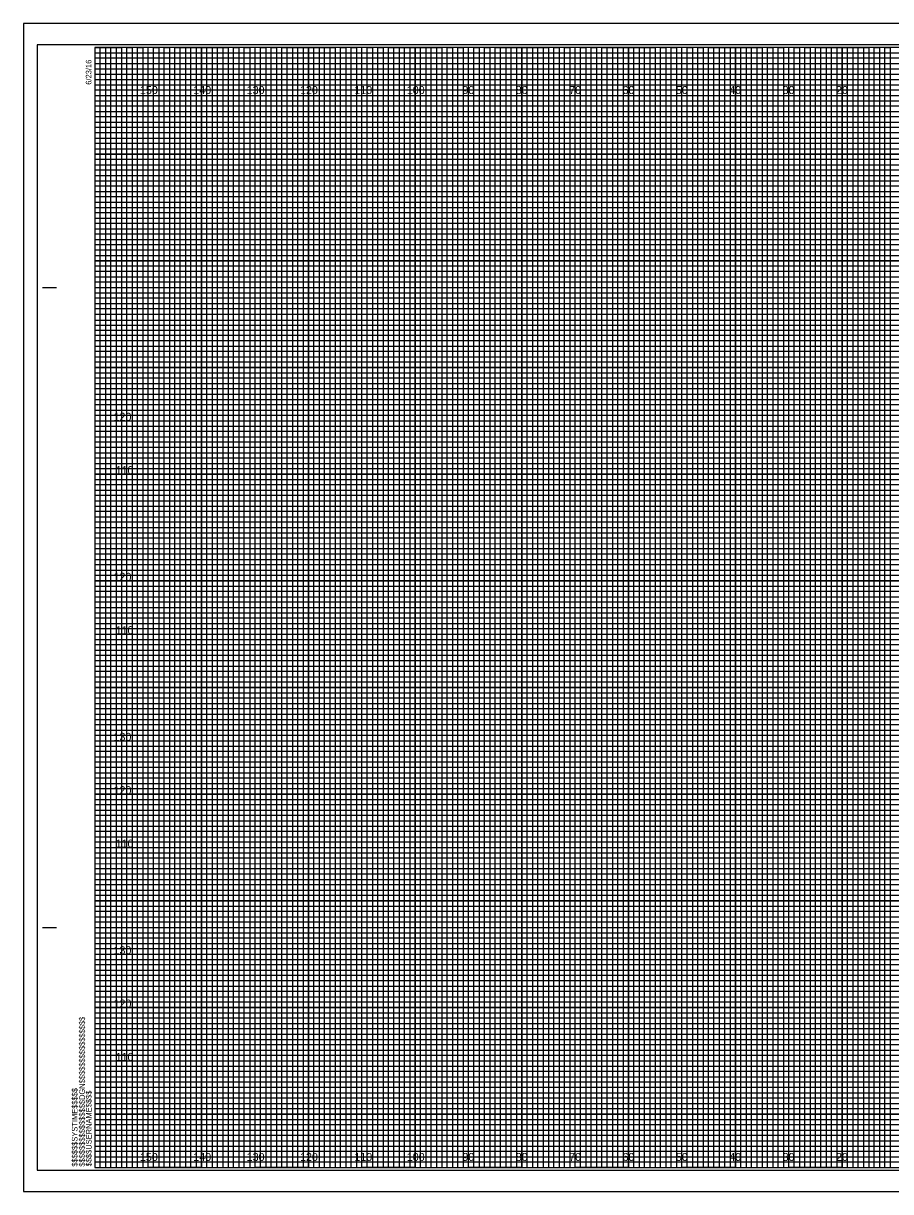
# Model space of a CAD drawing. Extents: x -13 to 323, y -5 to 215.
# Drawn here: x -13.4 to 149.1, y -4.5 to 214.5 of the extents above; entities that cross this region are included whole.
import ezdxf

# ---------------------------------------------------------------- set-up
doc = ezdxf.new("R2010")
doc.units = 0
for name, color, linetype in [('Prop XS Elevation Labels', 7, 'Continuous'), ('Prop XS Offset Labels', 7, 'Continuous'), ('Sheet Cross Section CELL', 7, 'Continuous'), ('Sheet Cross Section Grid Major CELL', 7, 'Continuous'), ('Sheet Cross Section Grid Middle CELL', 7, 'Continuous'), ('Sheet Cross Section Grid Minor 1 CELL', 7, 'Continuous'), ('Sheet Cross Section Grid Minor 2 CELL', 7, 'Continuous'), ('Sheet Cutting Line CELL', 7, 'Continuous'), ('Sheet DOT Grid CELL', 7, 'Continuous'), ('Sheet Plot Border Inside CELL', 7, 'Continuous'), ('Sheet Plot Border Outside CELL', 7, 'Continuous')]:
    doc.layers.add(name, color=color, linetype=linetype)

msp = doc.modelspace()

# ---------------------------------------------------------------- linework, layer by layer
at = {"layer": 'Sheet Cross Section CELL'}
for p, q in [((-9.8, 165), (-7.3, 165)), ((-9.7, 165), (-7.2, 165)), ((-9.8, 45), (-7.3, 45)), ((-9.7, 45), (-7.2, 45)), ((0, 0), (0, 0)), ((0, 0), (0, 0)), ((0, 0), (0, 0)), ((0, 0), (0, 0)), ((0, 0), (0, 0)), ((0, 0), (0, 0)), ((0, 0), (0, 0))]:
    msp.add_line(p, q, dxfattribs=at)
msp.add_lwpolyline([(320, 210), (0, 210), (0, 0), (320, 0)], close=True, dxfattribs=at)
at = {"layer": 'Sheet Cross Section Grid Major CELL'}
for p, q in [((10, 210), (0, 210)), ((10, 0), (10, 210)), ((30, 210), (20, 210)), ((20, 210), (20, 0)), ((30, 0), (30, 210)), ((50, 210), (40, 210)), ((40, 210), (40, 0)), ((50, 0), (50, 210)), ((70, 210), (60, 210)), ((60, 210), (60, 0)), ((70, 0), (70, 210)), ((90, 210), (80, 210)), ((80, 210), (80, 0)), ((90, 0), (90, 210)), ((110, 210), (100, 210)), ((100, 210), (100, 0)), ((110, 0), (110, 210)), ((130, 210), (120, 210)), ((120, 210), (120, 0)), ((130, 0), (130, 210)), ((150, 210), (140, 210)), ((140, 210), (140, 0)), ((20, 0), (10, 0)), ((40, 0), (30, 0)), ((60, 0), (50, 0)), ((80, 0), (70, 0)), ((100, 0), (90, 0)), ((120, 0), (110, 0)), ((140, 0), (130, 0))]:
    msp.add_line(p, q, dxfattribs=at)
for points in [[(0, 200), (320, 200), (320, 190), (0, 190)], [(0, 180), (320, 180), (320, 170), (0, 170)], [(0, 160), (320, 160), (320, 150), (0, 150)], [(0, 140), (320, 140), (320, 130), (0, 130)], [(0, 120), (320, 120), (320, 110), (0, 110)], [(0, 100), (320, 100), (320, 90), (0, 90)], [(0, 80), (320, 80), (320, 70), (0, 70)], [(0, 60), (320, 60), (320, 50), (0, 50)], [(0, 40), (320, 40), (320, 30), (0, 30)], [(0, 20), (320, 20), (320, 10), (0, 10)]]:
    msp.add_lwpolyline(points, dxfattribs=at)
at = {"layer": 'Sheet Cross Section Grid Middle CELL'}
for points in [[(0, 210), (5, 210), (5, 0), (15, 0), (15, 210), (25, 210), (25, 0), (35, 0), (35, 210), (45, 210), (45, 0), (55, 0), (55, 210), (65, 210), (65, 0), (75, 0), (75, 210), (85, 210), (85, 0), (95, 0), (95, 210), (105, 210), (105, 0), (115, 0), (115, 210), (125, 210), (125, 0), (135, 0), (135, 210), (145, 210), (145, 0), (155, 0)], [(0, 205), (275, 205)], [(0, 185), (320, 185), (320, 195), (0, 195)], [(0, 165), (320, 165), (320, 175), (0, 175)], [(0, 145), (320, 145), (320, 155), (0, 155)], [(0, 125), (320, 125), (320, 135), (0, 135)], [(0, 105), (320, 105), (320, 115), (0, 115)], [(0, 85), (320, 85), (320, 95), (0, 95)], [(0, 65), (320, 65), (320, 75), (0, 75)], [(0, 45), (320, 45), (320, 55), (0, 55)], [(0, 25), (320, 25), (320, 35), (0, 35)], [(0, 5), (320, 5), (320, 15), (0, 15)]]:
    msp.add_lwpolyline(points, dxfattribs=at)
at = {"layer": 'Sheet Cross Section Grid Minor 1 CELL'}
for p, q in [((0, 209), (260, 209)), ((260, 207.98), (0, 207.98)), ((0, 207.98), (0, 207)), ((0, 207), (260, 207)), ((260, 205.89), (0, 205.89)), ((0, 205.89), (0, 204)), ((0, 204), (320, 204))]:
    msp.add_line(p, q, dxfattribs=at)
for points in [[(0, 203), (270, 203), (320, 203), (320, 202), (0, 202)], [(0, 201), (320, 201), (320, 199), (0, 199)], [(0, 198), (320, 198), (320, 197), (0, 196.98)], [(0, 196), (320, 196), (320, 194), (0, 194)], [(0, 193), (320, 193), (320, 192), (0, 192)], [(0, 191), (320, 191), (320, 189), (0, 189)], [(0, 188), (320, 188), (320, 187), (0, 187)], [(0, 186), (320, 186), (320, 184), (0, 184)], [(0, 183), (320, 183), (320, 182), (0, 182)], [(0, 181), (320, 181), (320, 179), (0, 179)], [(0, 178), (320, 178), (320, 177), (0, 177)], [(0, 176), (320, 176), (320, 173.95), (320, 173), (320, 172), (0, 172)], [(0, 174), (320, 174), (320, 173), (0, 173)], [(0, 171), (320, 171), (320, 169), (0, 169.03)], [(0, 169.03), (320, 169), (320, 168), (0, 168)], [(0, 167), (320, 167), (320, 166), (0, 166)], [(0, 164), (320, 164), (320, 163), (0, 163)], [(0, 162), (320, 162), (320, 161), (0, 161)], [(-0.07, 158.89), (320, 158.89), (320, 157.88), (-0.07, 157.88)], [(0, 157), (320, 157), (320, 156), (0, 156)], [(0, 154), (320, 154), (320, 153), (0, 153)], [(0, 152), (320, 152), (320, 151), (0, 151)], [(0, 149), (320, 149), (320, 148), (0, 148)], [(0, 147), (320, 147), (320, 146), (0, 146)], [(0, 144), (320, 144), (320, 143), (0, 143)], [(0, 142), (320, 142), (320, 141), (0, 141)], [(0, 139), (320, 139), (319.99, 137.98), (0, 138)], [(0, 137), (320, 137), (320, 136), (0, 136)], [(0, 134), (320, 134), (320, 133), (0, 133)], [(0, 132), (320, 132), (320, 131), (0, 131)], [(0, 129), (320, 129), (320, 128), (0, 128)], [(0, 127), (320, 127), (320, 126), (0, 126)], [(0, 124), (320, 124), (320, 123), (0, 123)], [(0, 122), (320, 122), (320, 121), (0, 121)], [(0, 119), (320, 119), (320, 118), (0, 118)], [(0, 116.99), (320.07, 116.91), (320, 116), (0, 116)], [(0, 114), (320, 114), (320, 113), (0, 113)], [(0, 112), (320, 112), (320, 111), (0, 111)], [(0, 109), (320, 109), (320, 108), (0, 108)], [(0, 107), (320, 107), (320, 106), (0, 106)], [(0, 104), (320, 104), (320, 103), (0, 103)], [(0, 102), (320, 102), (320, 101), (0, 101)], [(0, 99), (320, 99), (320, 98), (0, 98)], [(0, 97), (320, 97), (320, 96), (0, 96)], [(0, 94), (320, 94), (320, 93), (0, 93)], [(0, 92), (320, 92), (320, 91), (0, 91)], [(0, 89), (320, 89), (320, 88), (0, 88)], [(0, 87), (320, 87), (320, 86), (0, 86)], [(0, 84), (320, 84), (320, 83), (0, 83)], [(0, 82), (320, 82), (320, 81), (0, 81)], [(0, 79), (320, 79), (319.99, 77.98), (0, 78)], [(0, 77), (320, 77), (320, 76), (0, 76)], [(0, 74), (320, 74), (320, 73), (0, 73)], [(0, 72), (320, 72), (320, 71), (0, 71)], [(0, 69), (320, 69), (320, 68), (0, 68)], [(0, 67), (320, 67), (320, 66), (0, 66)], [(0, 64), (320, 64), (320, 63), (0, 63)], [(0, 62), (320, 62), (320, 61), (0, 61)], [(0, 59), (320, 59), (320, 58), (0, 58)], [(0, 56.99), (320.07, 56.91), (320, 56), (0, 56)], [(0, 54), (320, 54), (320, 53), (0, 53)], [(0, 52), (320, 52), (320, 51), (0, 51)], [(0, 49), (320, 49), (320, 48), (0, 48)], [(0, 47), (320, 47), (320, 46), (0, 46)], [(0, 44), (320, 44), (320, 43), (0, 43)], [(0, 42), (320, 42), (320, 41), (0, 41)], [(0, 39), (320, 39), (320, 38), (0, 38)], [(0, 37), (320, 37), (320, 36), (0, 36)], [(0, 34), (320, 34), (320, 33), (0, 33)], [(0, 32), (320, 32), (320, 31), (0, 31)], [(0, 29), (320, 29), (320, 28), (0, 28)], [(0, 27), (320, 27), (320, 26), (0, 26)], [(0, 24), (320, 24), (320, 23), (0, 23)], [(0, 22), (320, 22), (320, 21), (0, 21)], [(0, 19), (320, 19), (320, 18), (0, 18)], [(0, 17), (320, 17), (320, 16), (0, 16)], [(0, 14), (320, 14), (320, 13), (0, 13)], [(0, 12), (320, 12), (320, 11), (0, 11)], [(0, 9), (320, 9), (320, 8), (0, 8)], [(0, 7), (320, 7), (320, 6), (0, 6)], [(0, 4), (320, 4), (320, 3), (0, 3)], [(0, 2), (320, 2), (320, 1), (0, 1)]]:
    msp.add_lwpolyline(points, dxfattribs=at)
at = {"layer": 'Sheet Cross Section Grid Minor 2 CELL'}
for points in [[(0, 0), (1, 0), (1, 210), (2, 210), (2, 0)], [(2, 0), (3, 0), (3, 210), (4, 210), (4, 0)], [(5, 0), (6, 0), (6, 210), (7, 210), (7, 0)], [(7, 0), (8, 0), (8, 210), (9, 210), (9, 0)], [(10, 0), (11, 0), (11, 210), (12, 210), (12, 0)], [(12, 0), (13, 0), (13, 210), (14, 210), (14, 0)], [(15, 0), (16, 0), (16, 210), (17, 210), (17, 0)], [(17, 0), (18, 0), (18, 210), (19, 210), (19, 0)], [(20, 0), (21, 0), (21, 210), (22, 210), (22, 0)], [(22, 0), (23, 0), (23, 210), (24, 210), (24, 0)], [(25, 0), (26, 0), (26, 210), (27, 210), (27, 0)], [(27, 0), (28, 0), (28, 210), (29, 210), (29, 0)], [(30, 0), (31, 0), (31, 210), (32, 210), (32, 0)], [(32, 0), (33, 0), (33, 210), (34, 210), (34, 0)], [(35, 0), (36, 0), (36, 210), (37, 210), (37, 0)], [(37, 0), (38, 0), (38, 210), (39, 210), (39, 0)], [(40, 0), (41, 0), (41, 210), (42, 210), (42, 0)], [(42, 0), (43, 0), (43, 210), (44, 210), (44, 0)], [(45, 0), (46, 0), (46, 210), (47, 210), (47, 0)], [(47, 0), (48, 0), (48, 210), (49, 210), (49, 0)], [(50, 0), (51, 0), (51, 210), (52, 210), (52, 0)], [(52, 0), (53, 0), (53, 210), (54, 210), (54, 0)], [(55, 0), (56, 0), (56, 210), (57, 210), (57, 0)], [(57, 0), (58, 0), (58, 210), (59, 210), (59, 0)], [(60, 0), (61, 0), (61, 210), (62, 210), (62, 0)], [(62, 0), (63, 0), (63, 210), (64, 210), (64, 0)], [(65, 0), (66, 0), (66, 210), (67, 210), (67, 0)], [(67, 0), (68, 0), (68, 210), (69, 210), (69, 0)], [(70, 0), (71, 0), (71, 210), (72, 210), (72, 0)], [(72, 0), (73, 0), (73, 210), (74, 210), (74, 0)], [(75, 0), (76, 0), (76, 210), (77, 210), (77, 0)], [(77, 0), (78, 0), (78, 210), (79, 210), (79, 0)], [(80, 0), (81, 0), (81, 210), (82, 210), (82, 0)], [(82, 0), (83, 0), (83, 210), (84, 210), (84, 0)], [(85, 0), (86, 0), (86, 210), (87, 210), (87, 0)], [(87, 0), (88, 0), (88, 210), (89, 210), (89, 0)], [(90, 0), (91, 0), (91, 210), (92, 210), (92, 0)], [(92, 0), (93, 0), (93, 210), (94, 210), (94, 0)], [(95, 0), (96, 0), (96, 210), (97, 210), (97, 0)], [(97, 0), (98, 0), (98, 210), (99, 210), (99, 0)], [(100, 0), (101, 0), (101, 210), (102, 210), (102, 0)], [(102, 0), (103, 0), (103, 210), (104, 210), (104, 0)], [(105, 0), (106, 0), (106, 210), (107, 210), (107, 0)], [(107, 0), (108, 0), (108, 210), (109, 210), (109, 0)], [(110, 0), (111, 0), (111, 210), (112, 210), (112, 0)], [(112, 0), (113, 0), (113, 210), (114, 210), (114, 0)], [(115, 0), (116, 0), (116, 210), (117, 210), (117, 0)], [(117, 0), (118, 0), (118, 210), (119, 210), (119, 0)], [(120, 0), (121, 0), (121, 210), (122, 210), (122, 0)], [(122, 0), (123, 0), (123, 210), (124, 210), (124, 0)], [(125, 0), (126, 0), (126, 210), (127, 210), (127, 0)], [(127, 0), (128, 0), (128, 210), (129, 210), (129, 0)], [(130, 0), (131, 0), (131, 210), (132, 210), (132, 0)], [(132, 0), (133, 0), (133, 210), (134, 210), (134, 0)], [(135, 0), (136, 0), (136, 210), (137, 210), (137, 0)], [(137, 0), (138, 0), (138, 210), (139, 210), (139, 0)], [(140, 0), (141, 0), (141, 210), (142, 210), (142, 0)], [(142, 0), (143, 0), (143, 210), (144, 210), (144, 0)], [(145, 0), (146, 0), (146, 210), (147, 210), (147, 0)], [(147, 0), (148, 0), (148, 210), (149, 210), (149, 0)]]:
    msp.add_lwpolyline(points, dxfattribs=at)
at = {"layer": 'Sheet Cutting Line CELL'}
for p, q in [((323.3, 214.5), (-13.4, 214.5)), ((-13.4, 214.5), (-13.4, -4.5)), ((-13.4, -4.5), (323.3, -4.5))]:
    msp.add_line(p, q, dxfattribs=at)
at = {"layer": 'Sheet DOT Grid CELL'}
for p, q in [((10, 0), (10, 210)), ((20, 0), (20, 210)), ((30, 0), (30, 210)), ((40, 0), (40, 210)), ((50, 0), (50, 210)), ((60, 0), (60, 210)), ((70, 0), (70, 210)), ((80, 0), (80, 210)), ((90, 0), (90, 210)), ((100, 0), (100, 210)), ((110, 0), (110, 210)), ((120, 0), (120, 210)), ((130, 0), (130, 210)), ((140, 0), (140, 210)), ((0, 200), (320, 200)), ((0, 190), (320, 190)), ((0, 180), (320, 180)), ((0, 170), (320, 170)), ((0, 160), (320, 160)), ((0, 150), (320, 150)), ((0, 140), (320, 140)), ((0, 130), (320, 130)), ((0, 120), (320, 120)), ((0, 110), (320, 110)), ((0, 100), (320, 100)), ((0, 90), (320, 90)), ((0, 80), (320, 80)), ((0, 70), (320, 70)), ((0, 60), (320, 60)), ((0, 50), (320, 50)), ((0, 40), (320, 40)), ((0, 30), (320, 30)), ((0, 20), (320, 20)), ((0, 10), (320, 10))]:
    msp.add_line(p, q, dxfattribs=at)
at = {"layer": 'Sheet Plot Border Inside CELL'}
msp.add_lwpolyline([(-10.8, -0.5), (322.4, -0.5), (322.4, 210.5), (-10.8, 210.5)], close=True, dxfattribs=at)
at = {"layer": 'Sheet Plot Border Outside CELL'}
msp.add_lwpolyline([(-13.4, -4.5), (323.3, -4.5), (323.3, 214.5), (-13.4, 214.5)], close=True, dxfattribs=at)

# ---------------------------------------------------------------- texts
at = {"layer": 'Prop XS Elevation Labels'}
for s, p in [('120', (3.5, 140)), ('110', (3.88, 130)), ('120', (3.5, 110)), ('110', (3.88, 100)), ('130', (3.49, 80)), ('120', (3.5, 70)), ('110', (3.88, 60)), ('130', (3.49, 40)), ('120', (3.5, 30)), ('110', (3.88, 20))]:
    msp.add_text(s, height=1.5, dxfattribs=at).set_placement(p)
at = {"layer": 'Prop XS Offset Labels'}
for s, p in [('150', (8.44, 201.25)), ('140', (18.44, 201.25)), ('130', (28.44, 201.25)), ('120', (38.44, 201.25)), ('110', (48.62, 201.25)), ('100', (58.44, 201.25)), ('90', (68.86, 201.25)), ('80', (78.86, 201.25)), ('70', (88.86, 201.25)), ('60', (98.86, 201.25)), ('50', (108.86, 201.25)), ('40', (118.86, 201.25)), ('30', (128.86, 201.25)), ('20', (138.86, 201.25)), ('150', (8.44, 1.25)), ('140', (18.44, 1.25)), ('130', (28.44, 1.25)), ('120', (38.44, 1.25)), ('110', (48.62, 1.25)), ('100', (58.44, 1.25)), ('90', (68.86, 1.25)), ('80', (78.86, 1.25)), ('70', (88.86, 1.25)), ('60', (98.86, 1.25)), ('50', (108.86, 1.25)), ('40', (118.86, 1.25)), ('30', (128.86, 1.25)), ('20', (138.86, 1.25))]:
    msp.add_text(s, height=1.5, dxfattribs=at).set_placement(p)
at = {"layer": 'Sheet Cross Section CELL'}
for s, p in [('6/23/16', (-0.65, 203)), ('$$$$$$$$$$$$$$$$DGN$$$$$$$$$$$$$$$$', (-1.88, 0.18)), ('$$$$$$SYSTIME$$$$$', (-3.26, 0.18)), ('$$$$USERNAME$$$$', (-0.62, 0.23))]:
    msp.add_text(s, height=1.05, rotation=90, dxfattribs=at).set_placement(p)

doc.saveas('drawing.dxf')
